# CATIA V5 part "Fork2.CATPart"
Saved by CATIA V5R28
Part number: Fork2
Material "DS Red": density 7860 kg/m3, Young's modulus 2e+11 Pa, Poisson ratio 0.266
Bounding box of the stored display mesh (mm): x -28.5 to 28.5, y -38 to 53.823, z -42 to 42
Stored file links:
  C:\Users\Parisa\Desktop\tarah sanat\Universal Coupling\Fork2.CATPart
  C:\Program Files\Dassault Systemes\B28\win_b64\startup\materials\red_env_512x512.jpg
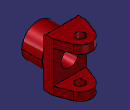
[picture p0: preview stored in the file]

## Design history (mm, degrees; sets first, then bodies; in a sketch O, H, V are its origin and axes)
Body1 "Fork2" (main body), material "DS Red"
  Sketch1 on zx-plane, origin (0, 0, 0), H (-1, 0, 0), V (0, 0, 1)
    line L1 (28.5, 42) -> (28.5, -42)
    line L2 (28.5, -42) -> (-28.5, -42)
    line L3 (-28.5, -42) -> (-28.5, 42)
    line L4 (-28.5, 42) -> (28.5, 42)
    length L1 = 84
    length L4 = 57
    vertical: L1 V, L3 V
    horizontal: L2 H, L4 H
    equidistance: L1 L3 O, L2 L4 O
  Pad1: profile Sketch1, direction (0, 1, 0), length 16
  Sketch2 on start face of Pad1, origin (0, 0, 0), H (1, 0, 0), V (0, 0, 1)
    circle A1 centre (0, 0) radius 28.5
    radius A1 = 28.5
  Pad2: profile Sketch2, direction (0, -1, 0), length 38
  Sketch3 on face of Pad1 from Sketch1.L4, origin (0, 0, 42), H (1, 0, 0), V (0, 1, 0)
    projected line E1 (-28.5, 16) -> (28.5, 16) from edge [face of Pad1 from Sketch1.L4 | end face of Pad1]
    axis line L1 (0, 16) -> (0, 34)
    point P3 (0, 16)
    circle A1 centre (0, 34) radius 8
    arc A2 centre (0, 34) radius 20 from (18.6299, 41.2751) to (-18.6299, 41.2751) ccw
    line L2 (28.5, 16) -> (18.6299, 41.2751)
    line L3 (-28.5, 16) -> (-18.6299, 41.2751)
    length L1 = 18
    radius A2 = 20
    radius A1 = 8
    midpoint: P3 E1
    vertical: L1 V
    tangency: L3 A2, A2 L2
  Pad3: profile Sketch3, direction (0, 0, -1), length 14
  Mirror1: of Pad3, about xy-plane
  Sketch4 on end face of Pad2, origin (0, -38, 0), H (1, 0, 0), V (0, 0, 1)
    arc A1 centre (0, 0) radius 15 from (-4, 14.4568) to (4, 14.4568) ccw
    line L1 (-4, 18.5) -> (4, 18.5)
    line L2 (4, 18.5) -> (4, 14.4568)
    line L3 (-4, 14.4568) -> (-4, 18.5)
    point P2 (4, 18.5)
    point P3 (4, 11.5)
    radius A1 = 15
    length L1 = 8
    distance P2 P3 = 7
    distance L1 H = 18.5
    horizontal: L1 H
    vertical: L2 V, L3 V
    symmetry: L2 L3 V
  Pocket1: profile Sketch4, direction (0, 1, 0), length 56
  Fillet1: radius 3, on edge [start face of Pad1 | face of Pad3]; edge [start face of Pad1 | face of Pad1]; edge [start face of Pad1 | face of Pad2 from Sketch2.A1] (x2)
